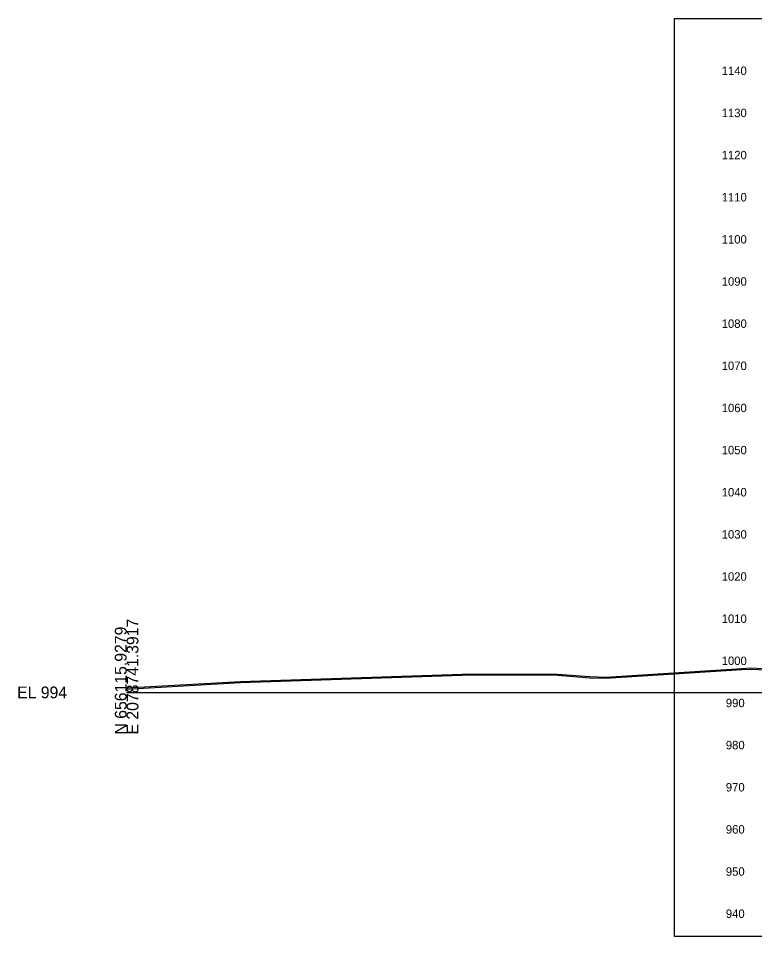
# Model space of a CAD drawing. Extents: x 1131015 to 1136271, y 133453 to 174329.
# Drawn here: x 1131014.8 to 1131189.5, y 160109.7 to 160327.6 of the extents above; entities that cross this region are included whole.
import ezdxf

# ---------------------------------------------------------------- set-up
doc = ezdxf.new("R2010")
doc.units = 0
for name, color, linetype in [('DESIGN - SHEET - Corner Text', 7, 'Continuous'), ('DESIGN - SHEET - Light Grid', 7, 'Continuous'), ('DESIGN - SHEET - Plot Shape', 7, 'Continuous'), ('SURVEY - GROUND - Bottom of Topsoil Layer', 7, 'Continuous'), ('SURVEY - GROUND - Top of Ground', 7, 'Continuous')]:
    doc.layers.add(name, color=color, linetype=linetype)

msp = doc.modelspace()

# ---------------------------------------------------------------- linework, layer by layer
at = {"layer": 'DESIGN - SHEET - Light Grid'}
msp.add_line((1131040.46, 160167.66), (1131340.46, 160167.66), dxfattribs=at)
at = {"layer": 'DESIGN - SHEET - Plot Shape'}
msp.add_lwpolyline([(1131170.46, 160327.6), (1131510.46, 160327.6), (1131510.46, 160109.72), (1131170.46, 160109.72)], close=True, dxfattribs=at)
at = {"layer": 'SURVEY - GROUND - Bottom of Topsoil Layer'}
for p, q in [((1131154.22, 160171.05), (1131186.48, 160173.1)), ((1131186.48, 160173.1), (1131188.57, 160173.21)), ((1131188.57, 160173.21), (1131194.16, 160172.96)), ((1131067.46, 160170.03), (1131122.45, 160171.81)), ((1131122.45, 160171.81), (1131142.71, 160171.75)), ((1131142.71, 160171.75), (1131150.4, 160171.16)), ((1131150.4, 160171.16), (1131154.22, 160171.05)), ((1131040.46, 160168.46), (1131067.46, 160170.03))]:
    msp.add_line(p, q, dxfattribs=at)
at = {"layer": 'SURVEY - GROUND - Top of Ground'}
for p, q in [((1131154.22, 160171.3), (1131186.48, 160173.35)), ((1131186.48, 160173.35), (1131188.57, 160173.46)), ((1131188.57, 160173.46), (1131194.16, 160173.21)), ((1131040.46, 160168.71), (1131067.46, 160170.28)), ((1131067.46, 160170.28), (1131122.45, 160172.06)), ((1131122.45, 160172.06), (1131142.71, 160172)), ((1131142.71, 160172), (1131150.4, 160171.41)), ((1131150.4, 160171.41), (1131154.22, 160171.3))]:
    msp.add_line(p, q, dxfattribs=at)

# ---------------------------------------------------------------- texts
at = {"layer": 'DESIGN - SHEET - Corner Text'}
for s, p in [('1140', (1131181.7, 160314.16)), ('1130', (1131181.7, 160304.16)), ('1120', (1131181.7, 160294.16)), ('1110', (1131181.7, 160284.16)), ('1100', (1131181.7, 160274.16)), ('1090', (1131181.7, 160264.16)), ('1080', (1131181.7, 160254.16)), ('1070', (1131181.7, 160244.16)), ('1060', (1131181.7, 160234.16)), ('1050', (1131181.7, 160224.16)), ('1040', (1131181.7, 160214.16)), ('1030', (1131181.7, 160204.16)), ('1020', (1131181.7, 160194.16)), ('1010', (1131181.7, 160184.16)), ('1000', (1131181.7, 160174.16)), ('990', (1131182.68, 160164.16)), ('980', (1131182.68, 160154.16)), ('970', (1131182.68, 160144.16)), ('960', (1131182.68, 160134.16)), ('950', (1131182.68, 160124.16)), ('940', (1131182.68, 160114.16))]:
    msp.add_text(s, height=2, dxfattribs=at).set_placement(p)
at = {"layer": 'DESIGN - SHEET - Light Grid'}
for s, p in [('E 2078741.3917', (1131043.26, 160157.66)), ('N 656115.9279', (1131040.46, 160157.66))]:
    msp.add_text(s, height=2.8, rotation=90, dxfattribs=at).set_placement(p)
msp.add_text('EL 994', height=2.8, dxfattribs=at).set_placement((1131014.46, 160166.26))

doc.saveas('drawing.dxf')
